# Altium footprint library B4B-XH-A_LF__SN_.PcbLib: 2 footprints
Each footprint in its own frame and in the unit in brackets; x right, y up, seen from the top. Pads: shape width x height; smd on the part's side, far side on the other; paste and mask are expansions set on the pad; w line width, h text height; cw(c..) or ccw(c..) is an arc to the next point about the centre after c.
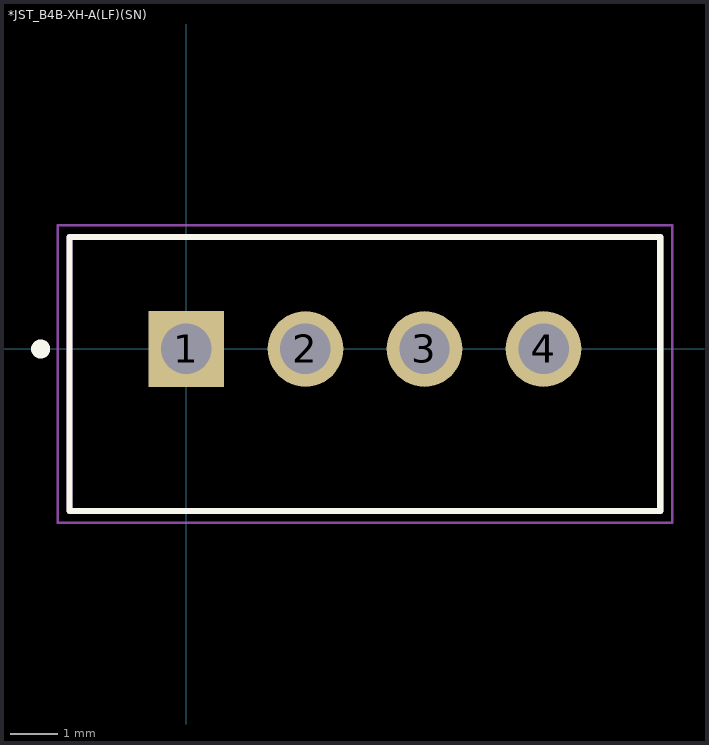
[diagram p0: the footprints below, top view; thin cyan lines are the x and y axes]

## *JST_B4B-XH-A(LF)(SN) [mm]
pads (4):
  rect 1.59x1.59 hole 1.06: 1(0,0)
  round 1.59 hole 1.06: 2(2.5,0) 3(5,0) 4(7.5,0)
Top Overlay:
  circle w0.2: c-3.06,0 r0.1
  lines w0.127: -2.45,-3.4 -2.45,2.35 9.95,2.35 9.95,-3.4 -2.45,-3.4
Mechanical 13:
  lines w0.127: -2.45,-3.4 -2.45,2.35 ; -2.45,-3.4 9.95,-3.4 ; -2.45,-3.4 -2.45,2.35 ; -2.45,-3.4 9.95,-3.4 ; -2.45,2.35 9.95,2.35 ; -2.45,2.35 9.95,2.35 ; 9.95,-3.4 9.95,2.35 ; 9.95,-3.4 9.95,2.35
Mechanical 15:
  lines w0.05: -2.7,-3.65 -2.7,2.6 10.2,2.6 10.2,-3.65 -2.7,-3.65

## PCBComponent_1 [mm]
